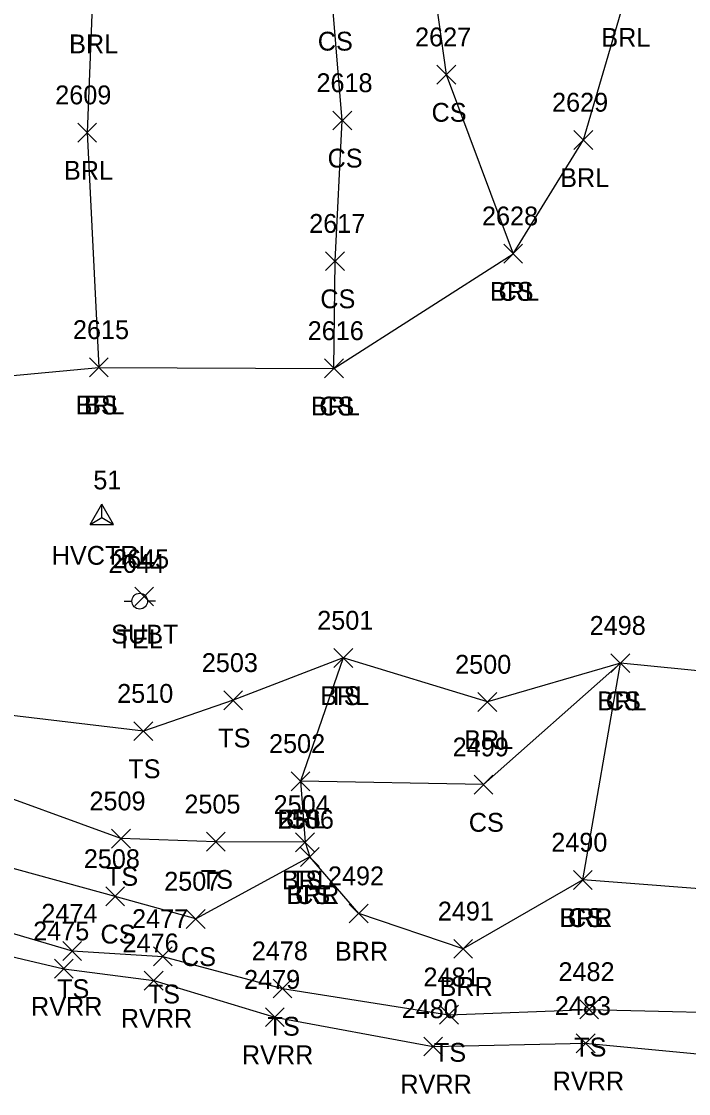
# Model space of a CAD drawing. Extents: x 1472022 to 1479249, y 777216 to 786527.
# Drawn here: x 1473752.5 to 1473823.2, y 779653.4 to 779767.2 of the extents above; entities that cross this region are included whole.
import ezdxf

# ---------------------------------------------------------------- set-up
doc = ezdxf.new("R2010")
doc.units = 0
for name, color, linetype in [('C_A', 7, 'Continuous'), ('C_I', 7, 'Continuous'), ('CPSM', 7, 'Continuous'), ('L_A', 7, 'Continuous'), ('L_I', 7, 'Continuous'), ('L_TIC', 7, 'Continuous'), ('LABL', 7, 'Continuous'), ('LAWE', 7, 'Continuous'), ('LELB', 7, 'Continuous'), ('LSOGP', 7, 'Continuous'), ('U_A', 7, 'Continuous'), ('U_I', 7, 'Continuous'), ('U_TIC', 7, 'Continuous'), ('UP', 7, 'Continuous')]:
    doc.layers.add(name, color=color, linetype=linetype)

msp = doc.modelspace()

# ---------------------------------------------------------------- linework, layer by layer
at = {"layer": 'CPSM'}
for p, q in [((1473759.76, 779713.83), (1473761.01, 779715.99)), ((1473762.26, 779713.83), (1473761.01, 779715.99)), ((1473761.01, 779714.55), (1473761.01, 779715.99)), ((1473759.76, 779713.83), (1473761.01, 779714.55)), ((1473761.01, 779714.55), (1473761.01, 779714.55)), ((1473761.01, 779714.55), (1473762.26, 779713.83)), ((1473759.76, 779713.83), (1473762.26, 779713.83))]:
    msp.add_line(p, q, dxfattribs=at)
at = {"layer": 'L_TIC'}
for points in [[(1473796.55, 779760.56), (1473798.55, 779762.56)], [(1473798.55, 779760.56), (1473796.55, 779762.56)], [(1473785.52, 779755.7), (1473787.52, 779757.7)], [(1473787.52, 779755.7), (1473785.52, 779757.7)], [(1473758.46, 779754.41), (1473760.46, 779756.41)], [(1473760.46, 779754.41), (1473758.46, 779756.41)], [(1473811.09, 779753.63), (1473813.09, 779755.63)], [(1473813.09, 779753.63), (1473811.09, 779755.63)], [(1473803.65, 779741.56), (1473805.65, 779743.56)], [(1473805.65, 779741.56), (1473803.65, 779743.56)], [(1473803.65, 779741.56), (1473805.65, 779743.56)], [(1473805.65, 779741.56), (1473803.65, 779743.56)], [(1473784.75, 779740.77), (1473786.75, 779742.77)], [(1473786.75, 779740.77), (1473784.75, 779742.77)], [(1473759.69, 779729.5), (1473761.69, 779731.5)], [(1473761.69, 779729.5), (1473759.69, 779731.5)], [(1473759.69, 779729.5), (1473761.69, 779731.5)], [(1473761.69, 779729.5), (1473759.69, 779731.5)], [(1473784.64, 779729.39), (1473786.64, 779731.39)], [(1473786.64, 779729.39), (1473784.64, 779731.39)], [(1473784.64, 779729.39), (1473786.64, 779731.39)], [(1473786.64, 779729.39), (1473784.64, 779731.39)], [(1473785.63, 779698.66), (1473787.63, 779700.66)], [(1473787.63, 779698.66), (1473785.63, 779700.66)], [(1473785.63, 779698.66), (1473787.63, 779700.66)], [(1473787.63, 779698.66), (1473785.63, 779700.66)], [(1473815.02, 779698.11), (1473817.02, 779700.11)], [(1473817.02, 779698.11), (1473815.02, 779700.11)], [(1473815.02, 779698.11), (1473817.02, 779700.11)], [(1473817.02, 779698.11), (1473815.02, 779700.11)], [(1473773.95, 779694.17), (1473775.95, 779696.17)], [(1473775.95, 779694.17), (1473773.95, 779696.17)], [(1473800.91, 779693.99), (1473802.91, 779695.99)], [(1473802.91, 779693.99), (1473800.91, 779695.99)], [(1473764.42, 779690.9), (1473766.42, 779692.9)], [(1473766.42, 779690.9), (1473764.42, 779692.9)], [(1473781.09, 779685.58), (1473783.09, 779687.58)], [(1473783.09, 779685.58), (1473781.09, 779687.58)], [(1473781.09, 779685.58), (1473783.09, 779687.58)], [(1473783.09, 779685.58), (1473781.09, 779687.58)], [(1473800.5, 779685.22), (1473802.5, 779687.22)], [(1473802.5, 779685.22), (1473800.5, 779687.22)], [(1473762.04, 779679.49), (1473764.04, 779681.49)], [(1473764.04, 779679.49), (1473762.04, 779681.49)], [(1473772.11, 779679.16), (1473774.11, 779681.16)], [(1473774.11, 779679.16), (1473772.11, 779681.16)], [(1473781.57, 779679.1), (1473783.57, 779681.1)], [(1473783.57, 779679.1), (1473781.57, 779681.1)], [(1473781.57, 779679.1), (1473783.57, 779681.1)], [(1473783.57, 779679.1), (1473781.57, 779681.1)], [(1473782.07, 779677.55), (1473784.07, 779679.55)], [(1473784.07, 779677.55), (1473782.07, 779679.55)], [(1473782.07, 779677.55), (1473784.07, 779679.55)], [(1473784.07, 779677.55), (1473782.07, 779679.55)], [(1473782.07, 779677.55), (1473784.07, 779679.55)], [(1473784.07, 779677.55), (1473782.07, 779679.55)], [(1473811.03, 779675.11), (1473813.03, 779677.11)], [(1473813.03, 779675.11), (1473811.03, 779677.11)], [(1473811.03, 779675.11), (1473813.03, 779677.11)], [(1473813.03, 779675.11), (1473811.03, 779677.11)], [(1473811.03, 779675.11), (1473813.03, 779677.11)], [(1473813.03, 779675.11), (1473811.03, 779677.11)], [(1473761.43, 779673.36), (1473763.43, 779675.36)], [(1473763.43, 779673.36), (1473761.43, 779675.36)], [(1473787.26, 779671.54), (1473789.26, 779673.54)], [(1473789.26, 779671.54), (1473787.26, 779673.54)], [(1473769.97, 779670.97), (1473771.97, 779672.97)], [(1473771.97, 779670.97), (1473769.97, 779672.97)], [(1473756.86, 779667.57), (1473758.86, 779669.57)], [(1473758.86, 779667.57), (1473756.86, 779669.57)], [(1473766.48, 779667), (1473768.48, 779669)], [(1473768.48, 779667), (1473766.48, 779669)], [(1473798.34, 779667.8), (1473800.34, 779669.8)], [(1473800.34, 779667.8), (1473798.34, 779669.8)], [(1473755.99, 779665.69), (1473757.99, 779667.69)], [(1473757.99, 779665.69), (1473755.99, 779667.69)], [(1473765.52, 779664.42), (1473767.52, 779666.42)], [(1473767.52, 779664.42), (1473765.52, 779666.42)], [(1473779.18, 779663.58), (1473781.18, 779665.58)], [(1473781.18, 779663.58), (1473779.18, 779665.58)], [(1473811.71, 779661.37), (1473813.71, 779663.37)], [(1473813.71, 779661.37), (1473811.71, 779663.37)], [(1473778.36, 779660.55), (1473780.36, 779662.55)], [(1473780.36, 779660.55), (1473778.36, 779662.55)], [(1473796.83, 779660.81), (1473798.83, 779662.81)], [(1473798.83, 779660.81), (1473796.83, 779662.81)], [(1473795.16, 779657.44), (1473797.16, 779659.44)], [(1473797.16, 779657.44), (1473795.16, 779659.44)], [(1473811.33, 779657.77), (1473813.33, 779659.77)], [(1473813.33, 779657.77), (1473811.33, 779659.77)]]:
    msp.add_lwpolyline(points, dxfattribs=at)
at = {"layer": 'LABL'}
for points in [[(1473771.17, 779820.24), (1473769.89, 779804.65), (1473766.6, 779787.48), (1473760, 779768.82), (1473759.46, 779755.41), (1473760.69, 779730.5), (1473785.64, 779730.39), (1473804.65, 779742.56), (1473812.09, 779754.63), (1473816.46, 779769.51), (1473817.76, 779781.14), (1473820.59, 779807.07)], [(1473812.03, 779676.11), (1473816.02, 779699.11), (1473801.91, 779694.99), (1473786.63, 779699.66), (1473782.09, 779686.58), (1473782.57, 779680.1), (1473783.07, 779678.55)], [(1473812.03, 779676.11), (1473799.34, 779668.8), (1473788.26, 779672.54), (1473783.07, 779678.55)]]:
    msp.add_lwpolyline(points, dxfattribs=at)
at = {"layer": 'LAWE'}
msp.add_lwpolyline([(1473721.66, 779684.59), (1473726.19, 779679.53), (1473730.08, 779672.96), (1473743.89, 779669.74), (1473756.99, 779666.69), (1473766.52, 779665.42), (1473779.36, 779661.55), (1473796.16, 779658.44), (1473812.33, 779658.77), (1473832.71, 779656.84), (1473845.94, 779659.73)], dxfattribs=at)
at = {"layer": 'LELB'}
for points in [[(1473785.64, 779730.39), (1473785.75, 779741.77), (1473786.52, 779756.7), (1473785.47, 779769.11), (1473786.43, 779783.88), (1473774.87, 779779.74), (1473769.69, 779800.17), (1473778.68, 779816.39), (1473798.61, 779816.02), (1473796.78, 779796.1), (1473795.9, 779773.2), (1473797.55, 779761.56), (1473804.65, 779742.56)], [(1473741.69, 779728.71), (1473760.69, 779730.5)], [(1473731.8, 779676.33), (1473743.79, 779672.74), (1473757.86, 779668.57), (1473767.48, 779668), (1473780.18, 779664.58), (1473797.83, 779661.81), (1473812.71, 779662.37), (1473833.32, 779661.88), (1473845.57, 779664.35), (1473842.75, 779671.88), (1473838.15, 779685.11), (1473839.47, 779701.41), (1473843.35, 779720.47)], [(1473786.63, 779699.66), (1473774.95, 779695.17), (1473765.42, 779691.9), (1473747.56, 779694), (1473737.29, 779694.42), (1473733.29, 779705.46), (1473727.15, 779710.1), (1473721.01, 779709.15), (1473718.63, 779702.18)], [(1473838.15, 779685.11), (1473826.38, 779698.09), (1473816.02, 779699.11), (1473801.5, 779686.22), (1473782.09, 779686.58)], [(1473782.57, 779680.1), (1473773.11, 779680.16), (1473763.04, 779680.49), (1473746.7, 779686.44), (1473735.12, 779689.52)], [(1473783.07, 779678.55), (1473770.97, 779671.97), (1473762.43, 779674.36), (1473745.53, 779679), (1473734.48, 779684.29)], [(1473842.75, 779671.88), (1473829.02, 779674.8), (1473812.03, 779676.11)]]:
    msp.add_lwpolyline(points, dxfattribs=at)
at = {"layer": 'LSOGP'}
msp.add_lwpolyline([(1473743.89, 779669.74), (1473756.99, 779666.69), (1473766.52, 779665.42), (1473779.36, 779661.55), (1473796.16, 779658.44), (1473812.33, 779658.77), (1473832.71, 779656.84)], dxfattribs=at)
at = {"layer": 'U_TIC'}
for points in [[(1473764.5, 779705.19), (1473766.5, 779707.19)], [(1473766.5, 779705.19), (1473764.5, 779707.19)]]:
    msp.add_lwpolyline(points, dxfattribs=at)
at = {"layer": 'UP'}
for p, q in [((1473763.37, 779705.68), (1473764.2, 779705.68)), ((1473765.03, 779705.69), (1473765.03, 779705.69)), ((1473766.7, 779705.69), (1473765.86, 779705.69)), ((1473765.86, 779705.69), (1473765.86, 779705.69)), ((1473766.7, 779705.69), (1473766.7, 779705.69))]:
    msp.add_line(p, q, dxfattribs=at)
msp.add_circle((1473765.03, 779705.69), 0.833, dxfattribs=at)

# ---------------------------------------------------------------- texts
at = {"layer": 'C_A'}
msp.add_text('HVCTRL', height=2, dxfattribs=at).set_placement((1473755.7, 779709.55))
at = {"layer": 'C_I'}
msp.add_text('51', height=2, dxfattribs=at).set_placement((1473760.11, 779717.55))
at = {"layer": 'L_A'}
for s, p in [('BRL', (1473757.54, 779763.82)), ('CS', (1473783.92, 779764.11)), ('BRL', (1473814, 779764.51)), ('CS', (1473795.99, 779756.56)), ('CS', (1473784.96, 779751.7)), ('BRL', (1473757, 779750.41)), ('BRL', (1473809.63, 779749.63)), ('BRL', (1473802.19, 779737.56)), ('CS', (1473803.09, 779737.56)), ('CS', (1473784.19, 779736.77)), ('BRL', (1473758.23, 779725.5)), ('BS', (1473759.13, 779725.5)), ('BRL', (1473783.19, 779725.39)), ('CS', (1473784.08, 779725.39)), ('BRL', (1473784.18, 779694.66)), ('TS', (1473785.04, 779694.66)), ('BRL', (1473813.57, 779694.11)), ('CS', (1473814.47, 779694.11)), ('TS', (1473773.36, 779690.17)), ('BRL', (1473799.45, 779689.99)), ('TS', (1473763.82, 779686.9)), ('BRL', (1473779.64, 779681.58)), ('CS', (1473780.53, 779681.58)), ('CS', (1473799.94, 779681.22)), ('TS', (1473761.45, 779675.49)), ('TS', (1473771.51, 779675.16)), ('BRL', (1473780.11, 779675.1)), ('TS', (1473780.98, 779675.1)), ('BRR', (1473780.56, 779673.55)), ('BRL', (1473780.62, 779673.55)), ('CS', (1473781.52, 779673.55)), ('BRR', (1473809.52, 779671.11)), ('BRL', (1473809.58, 779671.11)), ('CS', (1473810.47, 779671.11)), ('CS', (1473760.87, 779669.36)), ('CS', (1473769.41, 779666.97)), ('BRR', (1473785.74, 779667.54)), ('TS', (1473756.27, 779663.57)), ('BRR', (1473796.83, 779663.8)), ('TS', (1473765.89, 779663)), ('RVRR', (1473753.5, 779661.69)), ('RVRR', (1473763.03, 779660.42)), ('TS', (1473778.59, 779659.58)), ('TS', (1473796.24, 779656.81)), ('TS', (1473811.12, 779657.37)), ('RVRR', (1473775.87, 779656.55)), ('RVRR', (1473792.68, 779653.44)), ('RVRR', (1473808.84, 779653.77))]:
    msp.add_text(s, height=2, dxfattribs=at).set_placement(p)
at = {"layer": 'L_I'}
for s, p in [('2627', (1473794.24, 779764.56)), ('2618', (1473783.78, 779759.7)), ('2609', (1473756.07, 779758.41)), ('2629', (1473808.77, 779757.63)), ('2628', (1473801.34, 779745.56)), ('2628', (1473801.34, 779745.56)), ('2617', (1473783.01, 779744.77)), ('2615', (1473757.95, 779733.5)), ('2615', (1473757.95, 779733.5)), ('2616', (1473782.85, 779733.39)), ('2616', (1473782.85, 779733.39)), ('2501', (1473783.86, 779702.66)), ('2501', (1473783.86, 779702.66)), ('2498', (1473812.76, 779702.11)), ('2498', (1473812.76, 779702.11)), ('2503', (1473771.62, 779698.17)), ('2500', (1473798.49, 779697.99)), ('2510', (1473762.64, 779694.9)), ('2502', (1473778.75, 779689.58)), ('2502', (1473778.75, 779689.58)), ('2499', (1473798.23, 779689.22)), ('2509', (1473759.7, 779683.49)), ('2505', (1473769.77, 779683.16)), ('2504', (1473779.23, 779683.1)), ('2504', (1473779.23, 779683.1)), ('2506', (1473779.68, 779681.55)), ('2506', (1473779.68, 779681.55)), ('2506', (1473779.68, 779681.55)), ('2490', (1473808.69, 779679.11)), ('2490', (1473808.69, 779679.11)), ('2490', (1473808.69, 779679.11)), ('2508', (1473759.1, 779677.36)), ('2507', (1473767.63, 779674.97)), ('2492', (1473785, 779675.54)), ('2474', (1473754.6, 779671.57)), ('2491', (1473796.65, 779671.8)), ('2477', (1473764.22, 779671)), ('2475', (1473753.73, 779669.69)), ('2476', (1473763.21, 779668.42)), ('2478', (1473776.92, 779667.58)), ('2481', (1473795.13, 779664.81)), ('2482', (1473809.45, 779665.37)), ('2479', (1473776.1, 779664.55)), ('2480', (1473792.82, 779661.44)), ('2483', (1473809.07, 779661.77))]:
    msp.add_text(s, height=2, dxfattribs=at).set_placement(p)
at = {"layer": 'U_A'}
for s, p in [('SUBT', (1473762, 779701.19)), ('TEL', (1473762.59, 779700.69))]:
    msp.add_text(s, height=2, dxfattribs=at).set_placement(p)
at = {"layer": 'U_I'}
for s, p in [('2645', (1473762.2, 779709.19)), ('2644', (1473761.72, 779708.69))]:
    msp.add_text(s, height=2, dxfattribs=at).set_placement(p)

doc.saveas('drawing.dxf')
